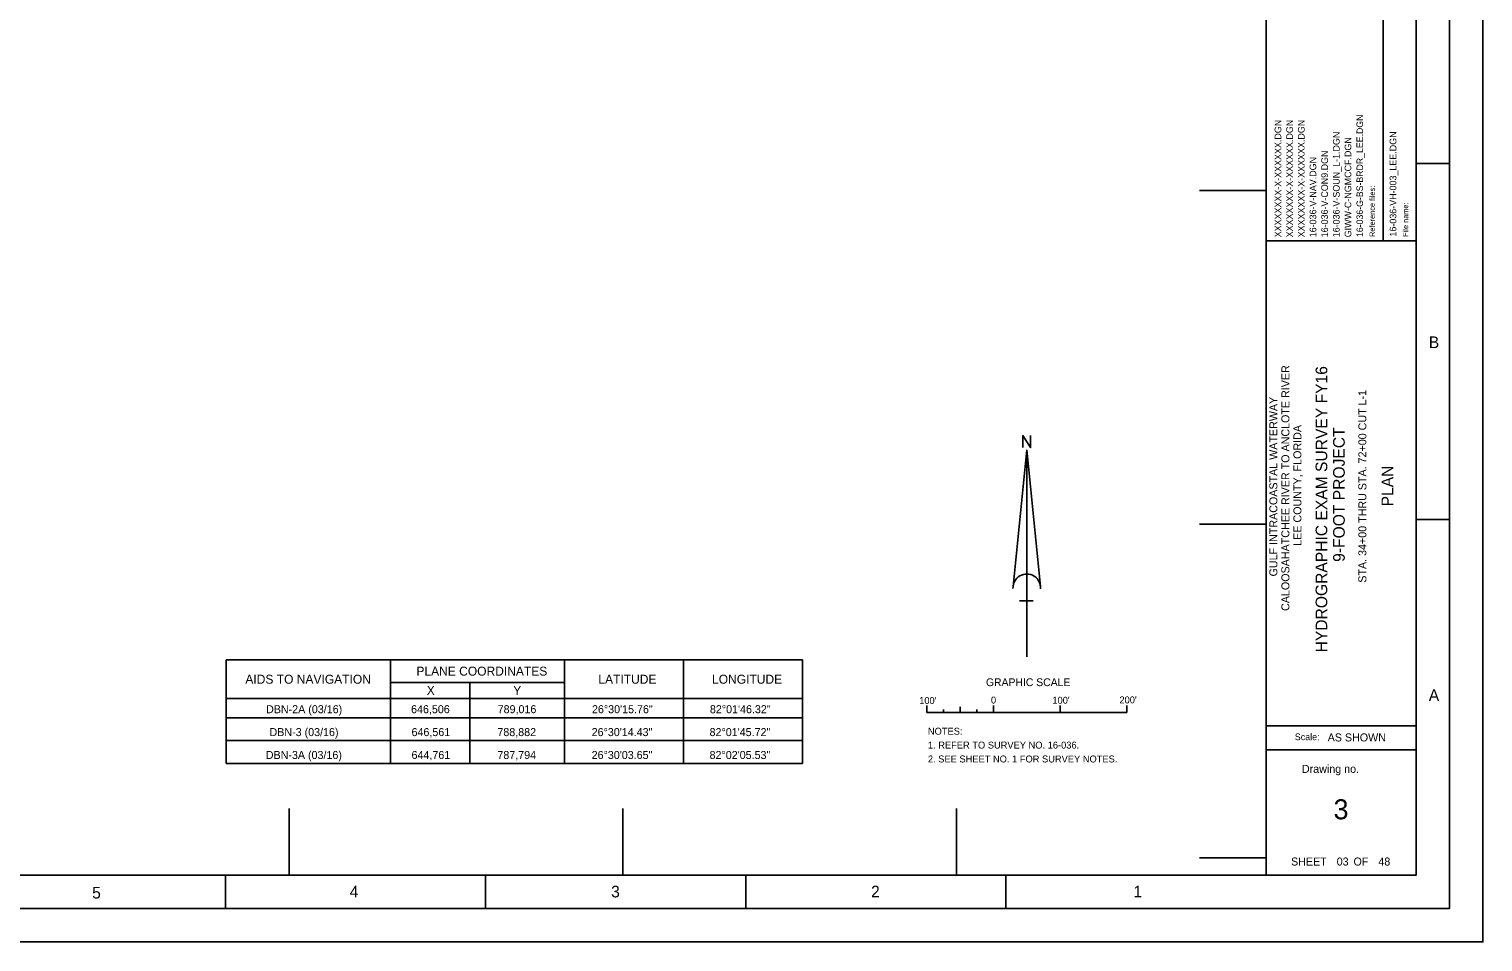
# Model space of a CAD drawing. Extents: x 643889 to 648289, y 786874 to 790274.
# Drawn here: x 646110 to 648289, y 786874 to 788242 of the extents above; entities that cross this region are included whole.
import ezdxf

# ---------------------------------------------------------------- set-up
doc = ezdxf.new("R2010")
doc.units = 0
for name, color, linetype in [('G-ANNO-NPLT', 7, 'Continuous'), ('G-ANNO-TEXT-DRWG', 7, 'Continuous'), ('G-ANNO-TEXT-PROJ', 7, 'Continuous'), ('G-ANNO-TEXT-TTLB', 7, 'Continuous'), ('G-ANNO-TTLB', 7, 'Continuous'), ('V-ANNO-NOTE', 7, 'Continuous'), ('V-ANNO-SCHD', 7, 'Continuous'), ('V-ANNO-SYMB', 7, 'Continuous'), ('V-TOPO-COOR-STAT', 7, 'Continuous')]:
    doc.layers.add(name, color=color, linetype=linetype)

msp = doc.modelspace()

# ---------------------------------------------------------------- linework, layer by layer
at = {"layer": 'G-ANNO-NPLT'}
msp.add_lwpolyline([(643889.2, 790274), (648289.2, 790274), (648289.2, 786874), (643889.2, 786874)], close=True, dxfattribs=at)
msp.add_lwpolyline([(648289.3, 786924), (648289.3, 786874), (648239.3, 786874)], dxfattribs=at)
at = {"layer": 'G-ANNO-TTLB'}
for p, q in [((647964.2, 790174), (647964.2, 786974)), ((648139.9, 788276.2), (648139.9, 787924.8)), ((648239.2, 788040.6), (648189.2, 788040.6)), ((647964.2, 787924.8), (648189.2, 787924.8)), ((648239.2, 787507.3), (648189.2, 787507.3)), ((647964.2, 787197.8), (648189.2, 787197.8)), ((647964.2, 787162.1), (648189.2, 787162.1)), ((646404.2, 786924), (646404.2, 786974)), ((646794.2, 786924), (646794.2, 786974)), ((647184.2, 786924), (647184.2, 786974)), ((647574.2, 786924), (647574.2, 786974))]:
    msp.add_line(p, q, dxfattribs=at)
for points in [[(643939.2, 786924), (648239.2, 786924), (648239.2, 790224), (643939.2, 790224)], [(648189.2, 790174), (644064.2, 790174), (644064.2, 786974), (648189.2, 786974)]]:
    msp.add_lwpolyline(points, close=True, dxfattribs=at)
at = {"layer": 'V-ANNO-NOTE'}
for p, q in [((647455.5, 787217.9), (647455.5, 787228.3)), ((647455.5, 787217.9), (647755.5, 787217.9)), ((647480.5, 787217.9), (647480.5, 787222.6)), ((647505.5, 787217.9), (647505.5, 787226.4)), ((647530.5, 787217.9), (647530.5, 787222.6)), ((647555.5, 787217.9), (647555.5, 787228.3)), ((647555.5, 787217.9), (647555.5, 787228.3)), ((647555.5, 787217.9), (647555.5, 787222.9)), ((647655.5, 787217.9), (647655.5, 787228.3)), ((647755.5, 787217.9), (647755.5, 787228.3))]:
    msp.add_line(p, q, dxfattribs=at)
at = {"layer": 'V-ANNO-SCHD'}
for p, q in [((646405.2, 787296.6), (647269.2, 787296.6)), ((646405.2, 787296.6), (646405.2, 787141.5)), ((646651.9, 787296.6), (646651.9, 787141.5)), ((646912.6, 787296.6), (646912.6, 787141.5)), ((647090.9, 787296.6), (647090.9, 787141.5)), ((647269.2, 787141.5), (647269.2, 787296.6)), ((646651.9, 787263), (646912.6, 787263)), ((646770.7, 787263), (646770.7, 787141.5)), ((646405.2, 787238.9), (647269.2, 787238.9)), ((646405.2, 787210), (647269.2, 787210)), ((646405.2, 787175.8), (647268.8, 787175.8)), ((646405.2, 787141.5), (647269.2, 787141.5))]:
    msp.add_line(p, q, dxfattribs=at)
at = {"layer": 'V-ANNO-SYMB'}
for p, q in [((647584.9, 787406.8), (647605.5, 787611.6)), ((647605.5, 787301.3), (647605.5, 787611.6)), ((647626.1, 787406.8), (647605.5, 787611.6)), ((647615.3, 787385.1), (647594.6, 787385.1))]:
    msp.add_line(p, q, dxfattribs=at)
msp.add_lwpolyline([(647599.8, 787614.9), (647599.8, 787633), (647611.1, 787614.9), (647611.1, 787633)], dxfattribs=at)
msp.add_arc((647605.5, 787404.7), 20.7, 355.2984, 182.0673, dxfattribs=at)
at = {"layer": 'V-TOPO-COOR-STAT'}
for p, q in [((647864.2, 788000), (647964.2, 788000)), ((647864.2, 787500), (647964.2, 787500)), ((646500, 786974), (646500, 787074)), ((647000, 786974), (647000, 787074)), ((647500, 786974), (647500, 787074)), ((647864.2, 787000), (647964.2, 787000))]:
    msp.add_line(p, q, dxfattribs=at)

# ---------------------------------------------------------------- texts
at = {"layer": 'G-ANNO-TEXT-DRWG'}
for s, height, p in [('XXXXXXXX-X-XXXXXX.DGN', 10, (647987, 787930.1)), ('XXXXXXXX-X-XXXXXX.DGN', 10, (648004.5, 787930.1)), ('XXXXXXXX-X-XXXXXX.DGN', 10, (648022, 787930.1)), ('16-036-V-SOUN_L-1.DGN', 10, (648074.5, 787930.1)), ('16-036-VH-003_LEE.DGN', 10, (648159.6, 787931.2)), ('16-036-V-CON9.DGN', 10, (648057, 787930.1)), ('GIWW-C-NGMCCF.DGN', 10, (648092, 787930.1)), ('16-036-V-NAV.DGN', 10, (648039.5, 787930.1)), ('STA. 34+00 THRU STA. 72+00 CUT L-1', 12, (648114.6, 787412.4)), ('PLAN', 17.5, (648154.8, 787526.8))]:
    msp.add_text(s, height=height, rotation=90, dxfattribs=at).set_placement(p)
for s, height, p in [('3', 30, (648065.5, 787057.8)), (' 03          48', 12, (648065.7, 786988.5))]:
    msp.add_text(s, height=height, dxfattribs=at).set_placement(p)
at = {"layer": 'G-ANNO-TEXT-PROJ'}
for s, height, p in [('16-036-G-BS-BRDR_LEE.DGN', 9.8, (648109.6, 787930.5)), ('CALOOSAHATCHEE RIVER TO ANCLOTE RIVER', 12, (647999.2, 787370.1)), ('HYDROGRAPHIC EXAM SURVEY FY16', 17.5, (648056, 787307.9)), ('GULF INTRACOASTAL WATERWAY', 12, (647981.2, 787421.8)), ('LEE COUNTY, FLORIDA', 12, (648017.2, 787467.8)), ('9-FOOT PROJECT', 17.5, (648082.2, 787443.7))]:
    msp.add_text(s, height=height, rotation=90, dxfattribs=at).set_placement(p)
at = {"layer": 'G-ANNO-TEXT-TTLB'}
for s, p in [('Reference files:', (648127.3, 787930.6)), ('File name:', (648177.3, 787930.8))]:
    msp.add_text(s, height=8, rotation=90, dxfattribs=at).set_placement(p)
for s, height, p in [('Scale:', 10, (648007.3, 787176.4)), ('AS SHOWN', 12, (648056.6, 787174.5)), ('Drawing no.', 12, (648018, 787127.4)), ('SHEET         OF', 12, (648001.7, 786988.5))]:
    msp.add_text(s, height=height, dxfattribs=at).set_placement(p)
at = {"layer": 'G-ANNO-TTLB'}
for s, p in [('B', (648208.2, 787764)), ('A', (648208.2, 787235.2)), ('5', (646204.4, 786939)), ('4', (646590.5, 786940.7)), ('3', (646982.4, 786940.7)), ('2', (647372.1, 786940.7)), ('1', (647765.3, 786940.7))]:
    msp.add_text(s, height=17.5, dxfattribs=at).set_placement(p)
at = {"layer": 'V-ANNO-NOTE'}
for s, height, p in [('GRAPHIC SCALE', 11.666, (647544.3, 787257.4)), ("100'", 10.42, (647444.2, 787230.6)), ('0', 10.4, (647551.8, 787231.3)), ("100'", 10.42, (647643.9, 787231)), ("200'", 10.42, (647744.4, 787231.5)), ('NOTES:', 10.42, (647457.3, 787184.6)), ('1. REFER TO SURVEY NO. 16-036.', 10.416, (647457.3, 787163.8)), ('2. SEE SHEET NO. 1 FOR SURVEY NOTES.', 10.416, (647457.3, 787143))]:
    msp.add_text(s, height=height, dxfattribs=at).set_placement(p)
at = {"layer": 'V-ANNO-SCHD'}
for s, height, p in [('AIDS TO NAVIGATION', 13.471, (646434.1, 787261)), ('PLANE COORDINATES', 13.471, (646690.5, 787273.1)), ('LATITUDE', 13.47, (646963.3, 787261)), ('LONGITUDE', 13.47, (647133.7, 787261)), ('X', 13.5, (646706, 787244.2)), ('Y', 13.5, (646835.7, 787244.2))]:
    msp.add_text(s, height=height, rotation=0.0001, dxfattribs=at).set_placement(p)
at = {"layer": 'V-ANNO-SYMB'}
for s, p in [('DBN-2A (03/16)', (646465.1, 787216.8)), ('646,506', (646682.5, 787216.8)), ('789,016', (646812.3, 787216.8)), ('26%%D30\'15.76"', (646953.7, 787216.8)), ('82%%D01\'46.32"', (647130.5, 787216.8)), ('DBN-3 (03/16)', (646470.3, 787182.5)), ('646,561', (646683.2, 787182.5)), ('788,882', (646811.9, 787182.5)), ('26%%D30\'14.43"', (646953.2, 787182.5)), ('82%%D01\'45.72"', (647130, 787182.5)), ('DBN-3A (03/16)', (646464.7, 787148.2)), ('644,761', (646683.2, 787148.2)), ('787,794', (646811.9, 787148.2)), ('26%%D30\'03.65"', (646953.2, 787148.2)), ('82%%D02\'05.53"', (647130, 787148.2))]:
    msp.add_text(s, height=12, dxfattribs=at).set_placement(p)

doc.saveas('drawing.dxf')
